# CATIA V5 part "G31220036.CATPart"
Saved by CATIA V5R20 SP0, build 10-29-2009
Part number: G31220036
Revision: 11
Definition: design
Nomenclature: G31220036
Source: made
Description: NOT SPECIFIED
Bounding box of the stored display mesh (mm): x -8 to 36, y -15.5 to 15.5, z -15.5 to 15.5
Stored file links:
  C:\Users\Raffaele\Desktop\3D X SITO CF\BOLEX\23-BUSH REF 312\G31220036.CATPart

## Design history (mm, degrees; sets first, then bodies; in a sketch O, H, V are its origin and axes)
Body1 "MANIFOLD_SOLID_BREP #10171" (main body)
  Solid1: solid without history
Body2 "MANIFOLD_SOLID_BREP #10314"
  Solid2: solid without history
Body3 "MANIFOLD_SOLID_BREP #10457"
  Solid3: solid without history
Body4 "MANIFOLD_SOLID_BREP #10600"
  Solid4: solid without history
Body5 "MANIFOLD_SOLID_BREP #10743"
  Solid5: solid without history
Body6 "MANIFOLD_SOLID_BREP #10888"
  Solid6: solid without history
Body7 "MANIFOLD_SOLID_BREP #11033"
  Solid7: solid without history
Body8 "MANIFOLD_SOLID_BREP #11178"
  Solid8: solid without history
Body9 "MANIFOLD_SOLID_BREP #11323"
  Solid9: solid without history
Body10 "MANIFOLD_SOLID_BREP #11468"
  Solid10: solid without history
Body11 "MANIFOLD_SOLID_BREP #11613"
  Solid11: solid without history
Body12 "MANIFOLD_SOLID_BREP #11758"
  Solid12: solid without history
Body13 "MANIFOLD_SOLID_BREP #11903"
  Solid13: solid without history
Body14 "MANIFOLD_SOLID_BREP #12048"
  Solid14: solid without history
Body15 "MANIFOLD_SOLID_BREP #12193"
  Solid15: solid without history
Body16 "MANIFOLD_SOLID_BREP #12338"
  Solid16: solid without history
Body17 "MANIFOLD_SOLID_BREP #12483"
  Solid17: solid without history
Body18 "MANIFOLD_SOLID_BREP #12628"
  Solid18: solid without history
Body19 "MANIFOLD_SOLID_BREP #12773"
  Solid19: solid without history
Body20 "MANIFOLD_SOLID_BREP #12918"
  Solid20: solid without history
Body21 "MANIFOLD_SOLID_BREP #13063"
  Solid21: solid without history
Body22 "MANIFOLD_SOLID_BREP #13210"
  Solid22: solid without history
Body23 "MANIFOLD_SOLID_BREP #13355"
  Solid23: solid without history
Body24 "MANIFOLD_SOLID_BREP #13500"
  Solid24: solid without history
Body25 "MANIFOLD_SOLID_BREP #13647"
  Solid25: solid without history
Body26 "MANIFOLD_SOLID_BREP #13792"
  Solid26: solid without history
Body27 "MANIFOLD_SOLID_BREP #13937"
  Solid27: solid without history
Body28 "MANIFOLD_SOLID_BREP #14082"
  Solid28: solid without history
Body29 "MANIFOLD_SOLID_BREP #14227"
  Solid29: solid without history
Body30 "MANIFOLD_SOLID_BREP #14372"
  Solid30: solid without history
Body31 "MANIFOLD_SOLID_BREP #14517"
  Solid31: solid without history
Body32 "MANIFOLD_SOLID_BREP #14660"
  Solid32: solid without history
Body33 "MANIFOLD_SOLID_BREP #14803"
  Solid33: solid without history
Body34 "MANIFOLD_SOLID_BREP #14948"
  Solid34: solid without history
Body35 "MANIFOLD_SOLID_BREP #15093"
  Solid35: solid without history
Body36 "MANIFOLD_SOLID_BREP #15238"
  Solid36: solid without history
Body37 "MANIFOLD_SOLID_BREP #15383"
  Solid37: solid without history
Body38 "MANIFOLD_SOLID_BREP #15530"
  Solid38: solid without history
Body39 "MANIFOLD_SOLID_BREP #15675"
  Solid39: solid without history
Body40 "MANIFOLD_SOLID_BREP #15820"
  Solid40: solid without history
Body41 "MANIFOLD_SOLID_BREP #15967"
  Solid41: solid without history
Body42 "MANIFOLD_SOLID_BREP #16112"
  Solid42: solid without history
Body43 "MANIFOLD_SOLID_BREP #16257"
  Solid43: solid without history
Body44 "MANIFOLD_SOLID_BREP #16402"
  Solid44: solid without history
Body45 "MANIFOLD_SOLID_BREP #16547"
  Solid45: solid without history
Body46 "MANIFOLD_SOLID_BREP #16692"
  Solid46: solid without history
Body47 "MANIFOLD_SOLID_BREP #16837"
  Solid47: solid without history
Body48 "MANIFOLD_SOLID_BREP #16982"
  Solid48: solid without history
Body49 "MANIFOLD_SOLID_BREP #17127"
  Solid49: solid without history
Body50 "MANIFOLD_SOLID_BREP #17272"
  Solid50: solid without history
Body51 "MANIFOLD_SOLID_BREP #17417"
  Solid51: solid without history
Body52 "MANIFOLD_SOLID_BREP #17564"
  Solid52: solid without history
Body53 "MANIFOLD_SOLID_BREP #17709"
  Solid53: solid without history
Body54 "MANIFOLD_SOLID_BREP #17854"
  Solid54: solid without history
Body55 "MANIFOLD_SOLID_BREP #18001"
  Solid55: solid without history
Body56 "MANIFOLD_SOLID_BREP #18144"
  Solid56: solid without history
Body57 "MANIFOLD_SOLID_BREP #18287"
  Solid57: solid without history
Body58 "MANIFOLD_SOLID_BREP #18432"
  Solid58: solid without history
Body59 "MANIFOLD_SOLID_BREP #18577"
  Solid59: solid without history
Body60 "MANIFOLD_SOLID_BREP #18722"
  Solid60: solid without history
Body61 "MANIFOLD_SOLID_BREP #18867"
  Solid61: solid without history
Body62 "MANIFOLD_SOLID_BREP #19012"
  Solid62: solid without history
Body63 "MANIFOLD_SOLID_BREP #19157"
  Solid63: solid without history
Body64 "MANIFOLD_SOLID_BREP #19300"
  Solid64: solid without history
Body65 "MANIFOLD_SOLID_BREP #19443"
  Solid65: solid without history
Body66 "MANIFOLD_SOLID_BREP #19588"
  Solid66: solid without history
Body67 "MANIFOLD_SOLID_BREP #19733"
  Solid67: solid without history
Body68 "MANIFOLD_SOLID_BREP #19878"
  Solid68: solid without history
Body69 "MANIFOLD_SOLID_BREP #20023"
  Solid69: solid without history
Body70 "MANIFOLD_SOLID_BREP #20170"
  Solid70: solid without history
Body71 "MANIFOLD_SOLID_BREP #20315"
  Solid71: solid without history
Body72 "MANIFOLD_SOLID_BREP #20460"
  Solid72: solid without history
Body73 "MANIFOLD_SOLID_BREP #20607"
  Solid73: solid without history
